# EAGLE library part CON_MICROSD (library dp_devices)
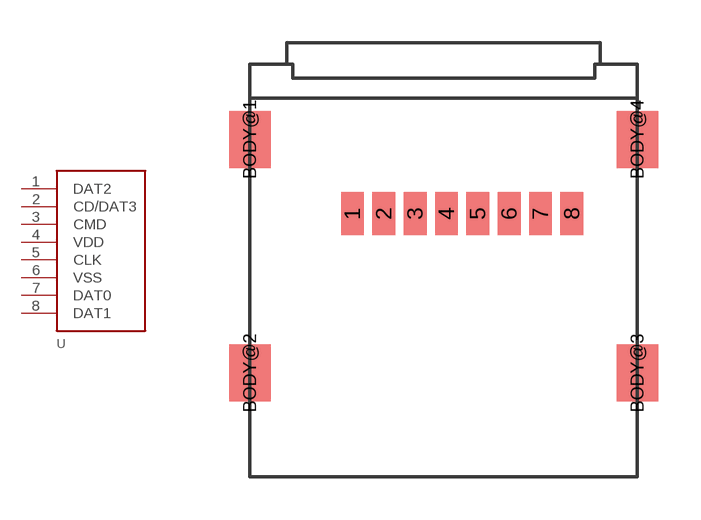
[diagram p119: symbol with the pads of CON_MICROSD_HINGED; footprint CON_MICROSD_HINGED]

Designator prefix -

## CON_MICROSDHINGED  [CON_MICROSD_HINGED]
1  DAT2
2  CD/DAT3
3  CMD
4  VDD
5  CLK
6  VSS
7  DAT0
8  DAT1

## Footprint CON_MICROSD_HINGED (pad centres in mm)
smd 0.8 x 1.5: 1 -3.2,2.6; 2 -2.1,2.6; 3 -1,2.6; 4 0.1,2.6; 5 1.2,2.6; 6 2.3,2.6; 7 3.4,2.6; 8 4.5,2.6
smd 1.45 x 2: BODY@1 -6.8,5.2; BODY@2 -6.8,-3; BODY@3 6.8,-3; BODY@4 6.8,5.2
